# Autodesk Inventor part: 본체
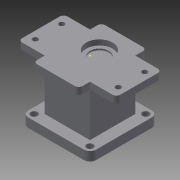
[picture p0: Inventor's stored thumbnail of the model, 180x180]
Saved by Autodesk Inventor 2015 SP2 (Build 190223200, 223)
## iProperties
Created: 2015-06
Part Number: 본체
Material: 일반
Document SubType Name: Modeling
Designer: AMC
Density: 1 g/cm^3
Appearance: 기본값
Author: AMC
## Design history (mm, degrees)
sketch "스케치1"
  geometry: L1 (-45, 45)-(45, 45); L2 (45, 45)-(45, -45); L3 (45, -45)-(-45, -45); L4 (-45, -45)-(-45, 45); 3 further points
  constraints: 8 end point, 2 midpoint, 2 parallel, 1 horizontal, 1 horizontal alignment, 1 perpendicular, 1 vertical alignment
  dimensions: "d0" = 90 distance of L1.start L1.end; "d1" = 90 distance of L1.end L2.end
extrude "돌출1" new body sketch "스케치1" distance "d2" = 12; taper "d3" = 0 deg
sketch "스케치2"
  geometry: L1 (-30, 30)-(30, 30); L2 (30, 30)-(30, -30); L3 (30, -30)-(-30, -30); L4 (-30, -30)-(-30, 30); 3 further points
  constraints: 8 end point, 2 midpoint, 2 parallel, 1 horizontal, 1 horizontal alignment, 1 perpendicular, 1 vertical alignment
  dimensions: "d4" = 60 distance of L1.start L1.end; "d5" = 60 distance of L1.end L2.end
extrude "돌출2" join sketch "스케치2" distance "d6" = 58; taper "d7" = 0 deg
sketch "스케치6"
  geometry: L1 (65, 30)-(65, -30); L2 (-65, -30)-(-65, 30); L3 (-30, 45)-(30, 45); L4 (30, -45)-(-30, -45); L5 (-65, 30)-(-30, 30); L6 (30, 30)-(65, 30); L7 (-30, -45)-(-30, -30); L8 (-30, 30)-(-30, 45); L9 (30, 45)-(30, 30); L10 (30, -30)-(30, -45); L11 (65, -30)-(30, -30); L12 (-30, -30)-(-65, -30); 10 further points
  constraints: 24 end point, 10 parallel, 8 midpoint, 4 perpendicular, 3 horizontal, 3 horizontal alignment, 3 vertical alignment
  dimensions: "d28" = 60 distance of L3.start L3.end; "d29" = 60 distance of L1.start L1.end; "d30" = 130 distance of L1.start L2.end; "d32" = 65 distance from line of point (0, 45) L1; "d33" = 60 distance of L4.start L4.end; "d34" = 45 distance of point (0, -45) point (0, 0); "d35" = 45 distance from line of point (0, 0) L3
extrude "돌출4" join sketch "스케치6" distance "d36" = 9; taper "d37" = 0 deg
sketch "스케치7"
  geometry: 1 further point
fillet "모깎기3" dims "d39" = 8
hole "구멍2" diameter "d42" = 9; stored, may be unused: countersink angle "d46" = 90 deg, drill point angle "d48" = 118 deg; dims "d40" = 10, "d41" = 10, "d43" = 6, "d44" = 4, "d45" = 2, "d47" = 8
sketch "스케치8"
  geometry: 1 further point
sketch "스케치9"
  geometry: 1 further point
sketch "스케치12"
  geometry: L1 (65, -30)-(65, 30) reference; L2 (65, 30)-(30, 30) reference; 2 further points
  dimensions: "d57" = 10 distance from line of L1 point (55, 17.5); "d58" = 12.5 distance from line of point (55, 17.5) L2
hole "구멍3" sketch "스케치12" at (55, 17.5) diameter "d59" = 7; stored, may be unused: countersink angle "d63" = 90 deg, drill point angle "d65" = 118 deg; dims "d60" = 6, "d61" = 4, "d62" = 2, "d64" = 8
fillet "모깎기4" dims "d72" = 5
sketch "스케치13"
  geometry: C1 r 39 at (0, 0); 1 further point
  constraints: 1 centre point, 1 coincident
  dimensions: "d73" = 78 diameter of C1
extrude "돌출5" cut sketch "스케치13" distance "d74" = 9; taper "d75" = 0 deg
sketch "스케치14"
  geometry: C1 r 17.5 at (0, 12.5); 1 further point
  constraints: 1 centre point
  dimensions: "d76" = 35 diameter of C1; "d77" = 12.5 distance of point (0, 0) C1.centre
extrude "돌출6" cut sketch "스케치14" distance "d78" = 7; taper "d79" = 0 deg
sketch "스케치15"
  geometry: C1 r 12.5 at (0, 0); 1 further point
  constraints: 1 centre point
  dimensions: "d80" = 25 diameter of C1
extrude "돌출7" cut sketch "스케치15" distance "d81" = 2; taper "d82" = 0 deg
sketch "스케치17"
  geometry: 1 further point
node "솔리드1"
pattern_linear "직사각형 패턴1" dims "d51" = 74
pattern_linear "직사각형 패턴2" dims "d54" = 74
pattern_linear "직사각형 패턴3" dims "d68" = -35
